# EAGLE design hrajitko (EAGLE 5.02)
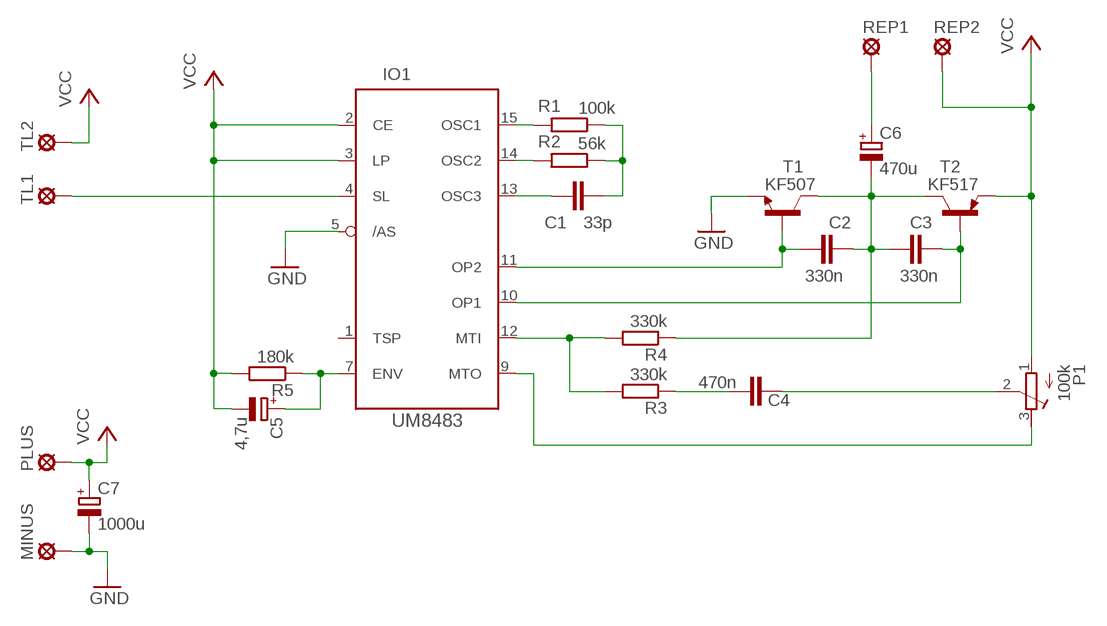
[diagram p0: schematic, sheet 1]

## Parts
C1  33p  C-EU025-030X050  [C025-030X050]
C2  330n  C-EU025-030X050  [C025-030X050]
C3  330n  C-EU025-030X050  [C025-030X050]
C4  470n  C-EU025-030X050  [C025-030X050]
C5  4,7u  CPOL-EUE2.5-6  [E2,5-6]
C6  470u  CPOL-EUE5-10.5  [E5-10,5]
C7  1000u  CPOL-EUE5-10.5  [E5-10,5]
IO1  UM8483  UM3483  [DIL16]
MINUS  SE13  [SE13]
P1  100k  R-TRIMM3339P  [RTRIM3339P]
PLUS  SE13  [SE13]
R1  100k  R-EU_0207/10  [0207/10]
R2  56k  R-EU_0207/10  [0207/10]
R3  330k  R-EU_0207/10  [0207/10]
R4  330k  R-EU_0207/10  [0207/10]
R5  180k  R-EU_0207/10  [0207/10]
REP1  SE13  [SE13]
REP2  SE13  [SE13]
T1  KF507  [TO18]
T2  KF517  [TO18]
TL1  SE13  [SE13]
TL2  SE13  [SE13]

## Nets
GND: C7.- IO1.5(/AS) MINUS.MP T1.1(E)
N$1: IO1.14(OSC2) R2.2
N$2: IO1.15(OSC1) R1.2
N$3: C1.2 IO1.13(OSC3)
N$4: C1.1 R1.1 R2.1
N$5: C5.+ IO1.7(ENV) R5.1
N$6: C2.2 IO1.11(OP2) T1.2(B)
N$7: C3.1 IO1.10(OP1) T2.2(B)
N$8: C2.1 C3.2 C6.- R4.1 T1.3(C) T2.3(C)
N$9: IO1.12(MTI) R3.2 R4.2
N$10: C4.2 R3.1
N$11: C4.1 P1.2(S)
N$12: C6.+ REP1.MP
N$13: IO1.4(SL) TL1.MP
N$14: IO1.9(MTO) P1.3(A)
VCC: C5.- C7.+ IO1.2(CE) IO1.3(LP) P1.1(E) PLUS.MP R5.2 REP2.MP T2.1(E) TL2.MP
Unconnected: IO1.1(TSP)

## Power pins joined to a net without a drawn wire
GND: IO1.8(GND)
VCC: IO1.16(VCC)

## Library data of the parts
C1-C4 = rcl:C-EU: CAPACITOR, European symbol
C5-C7 = rcl:CPOL-EU: POLARIZED CAPACITOR, European symbol
IO1 = sasina_knihovna:UM3483
MINUS PLUS REP1 REP2 TL1 TL2 = solpad:SE13: SOLDER PAD
P1 = rcl:R-TRIMM: Trimm resistor
R1-R5 = rcl:R-EU_: RESISTOR, European symbol
T1 = sasina_knihovna:KF507
T2 = sasina_knihovna:KF517

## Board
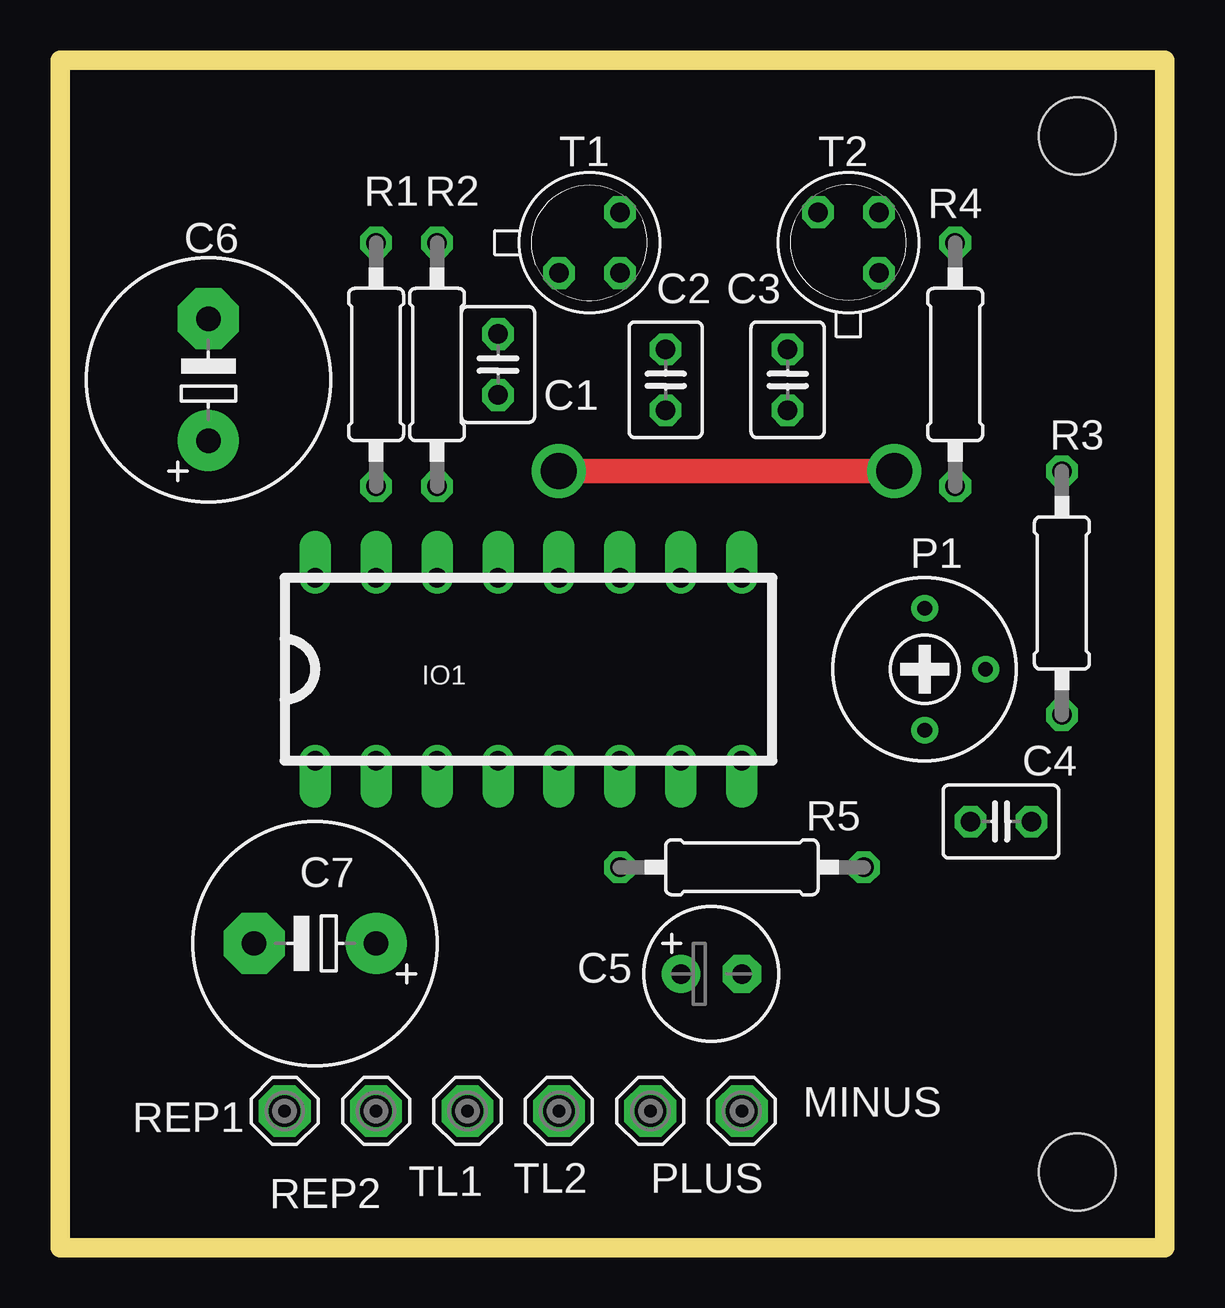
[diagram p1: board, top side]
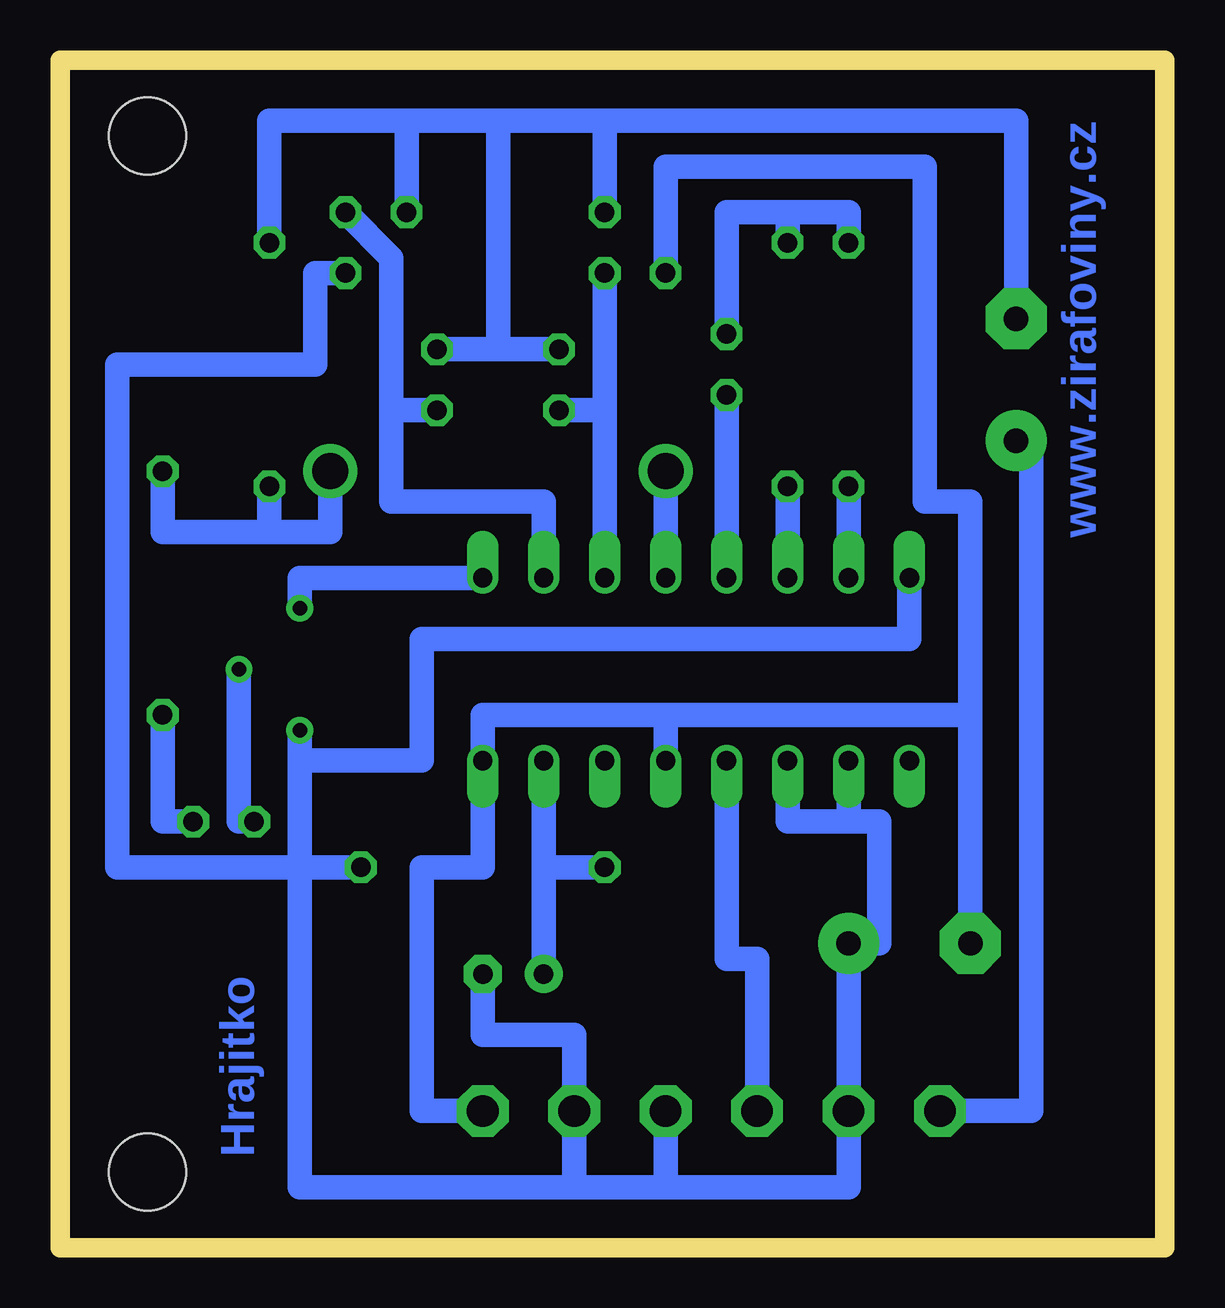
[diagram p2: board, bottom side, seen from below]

Size 46.02 x 49.52 mm. Coordinates in mm from the lower left corner, seen from the top.
Outline: 0,0 46.02,0 46.02,49.52 0,49.52 0,0
Copper layers (1*16): Top 0.035mm / dielectric 1.5mm / Bottom 0.035mm
Design rules "default": minimum track width 10mil, minimum drill 24mil, track to track 8mil, track to pad 8mil, pad to pad 8mil, via to via 8mil, smd to smd 8mil, copper to edge 40mil, drill to drill 8mil, minimum pad ring 10mil, minimum via ring 8mil, stop-mask expansion 4mil, vias tented up to drill 0mil, thermal gap 10mil
Holes 3.2 mm at 42.38,46.35 42.38,3.17

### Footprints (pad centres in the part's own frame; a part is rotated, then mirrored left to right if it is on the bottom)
C025-030X050 = drill 0.813 octagon: 1 -1.27,0; 2 1.27,0
E2,5-6 = drill 0.813 pad 1.6 round: + -1.27,0 | drill 0.813 pad 1.6 octagon: - 1.27,0
E5-10,5 = drill 1.016 pad 2.54 round: + -2.54,0 | drill 1.016 pad 2.54 octagon: - 2.54,0
DIL16 = drill 0.8 offset: 1 0,-1.27; 2 2.54,-1.27; 3 5.08,-1.27; 4 7.62,-1.27; 5 10.16,-1.27; 6 12.7,-1.27; 7 15.24,-1.27; 8 17.78,-1.27; 9 17.78,6.35; 10 15.24,6.35; 11 12.7,6.35; 12 10.16,6.35; 13 7.62,6.35; 14 5.08,6.35; 15 2.54,6.35; 16 0,6.35
SE13 = drill 1.321 pad 2.159 octagon: MP 0,0
RTRIM3339P = drill 0.61 round: 1 -2.54,0; 2 0,-2.54; 3 2.54,0
0207/10 = drill 0.813 octagon: 1 -5.08,0; 2 5.08,0
TO18 = drill 0.813 octagon: 1 -1.27,-1.27; 2 1.27,-1.27; 3 1.27,1.27

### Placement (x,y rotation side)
C1  18.25,36.83 270 top
C2  25.23,36.19 270 top
C3  30.31,36.19 90 top
C4  39.2,17.77 0 top
C5  27.14,11.43 0 top
C6  6.18,36.19 90 top
C7  10.63,12.7 180 top
IO1  10.63,21.58 0 top
MINUS  28.41,5.71 0 top
P1  36.03,24.12 90 top
PLUS  24.6,5.71 0 top
R1  13.17,36.83 270 top
R2  15.71,36.83 270 top
R3  41.74,27.3 90 top
R4  37.3,36.83 270 top
R5  28.41,15.87 0 top
REP1  9.36,5.71 0 top
REP2  13.17,5.71 0 top
T1  22.06,41.91 0 top
T2  32.85,41.91 90 top
TL1  16.98,5.71 0 top
TL2  20.79,5.71 0 top

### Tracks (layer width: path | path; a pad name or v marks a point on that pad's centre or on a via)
GND
  Bottom 0.813: 8.09,31.11 8.09,22.22
  Bottom 1.016: 8.09,22.22 20.79,22.22 | 20.79,22.22 28.41,22.22 IO1.8 28.41,15.87 30.95,15.87 30.95,5.71 MINUS.MP | T1.1 20.79,45.08 10,45.08 10,31.11 8.09,31.11 C7.- | 20.79,22.22 IO1.5
N$1
  Bottom 1.016: IO1.14 R2.2
N$2
  Bottom 1.016: IO1.15 R1.2
N$3
  Bottom 1.016: IO1.13 C1.2
N$4
  Bottom 1.016: C1.1 18.25,43.18 15.71,43.18 | 15.71,43.18 13.17,43.18 R1.1 | 15.71,43.18 R2.1
N$5
  Bottom 1.016: 25.87,15.87 IO1.7 | 25.87,15.87 R5.1 | C5.+ 25.87,13.33 25.87,15.87
N$6
  Bottom 1.016: IO1.11 23.33,34.92 | 23.33,34.92 T1.2 | 23.33,34.92 C2.2
N$7
  Bottom 1.016: 32.22,34.92 32.22,31.11 25.87,31.11 IO1.10 | 32.22,34.92 32.22,41.27 T2.2 | 32.22,34.92 C3.1
N$8
  Bottom 1.016: 23.33,46.98 T1.3 | 23.33,46.98 27.77,46.98 | 27.77,46.98 31.58,46.98 | 31.58,46.98 T2.3 | 27.77,37.46 C2.1 | 27.77,37.46 C3.2 | 27.77,46.98 27.77,37.46 | 31.58,46.98 37.3,46.98 R4.1 | C6.- 6.18,46.98 23.33,46.98
N$9  (via drill 1.5)
  Top 1.016: v20.79,32.38 v34.76,32.38
  Bottom 1.016: R3.2 41.74,29.84 37.3,29.84 | 37.3,29.84 R4.2 | IO1.12 v20.79,32.38 | v34.76,32.38 34.76,29.84 37.3,29.84
N$10
  Bottom 1.016: C4.2 41.74,17.77 R3.1
N$11
  Bottom 1.016: P1.2 38.57,17.77 C4.1
N$12
  Bottom 1.016: REP1.MP 5.55,5.71 5.55,33.65 C6.+
N$13
  Bottom 1.016: IO1.4 18.25,12.06 16.98,12.06 TL1.MP
N$14
  Bottom 1.016: IO1.9 36.03,27.93 P1.3
VCC
  Bottom 1.016: IO1.16 10.63,25.39 30.95,25.39 30.95,20.31 36.03,20.31 | 20.79,2.54 13.17,2.54 REP2.MP C7.+ 11.9,12.7 11.9,17.77 13.17,17.77 | T2.1 35.39,40.64 35.39,36.83 43.65,36.83 43.65,15.87 36.03,15.87 | 36.03,15.87 36.03,20.31 | 36.03,20.31 P1.1 | 20.79,2.54 24.6,2.54 | 24.6,2.54 36.03,2.54 36.03,15.87 | 36.03,15.87 R5.2 | 20.79,2.54 TL2.MP | 24.6,2.54 PLUS.MP 24.6,8.89 28.41,8.89 C5.- | IO1.3 15.71,17.77 13.17,17.77 | 13.17,17.77 IO1.2

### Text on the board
Bottom: www.zirafoviny.cz | Hrajitko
